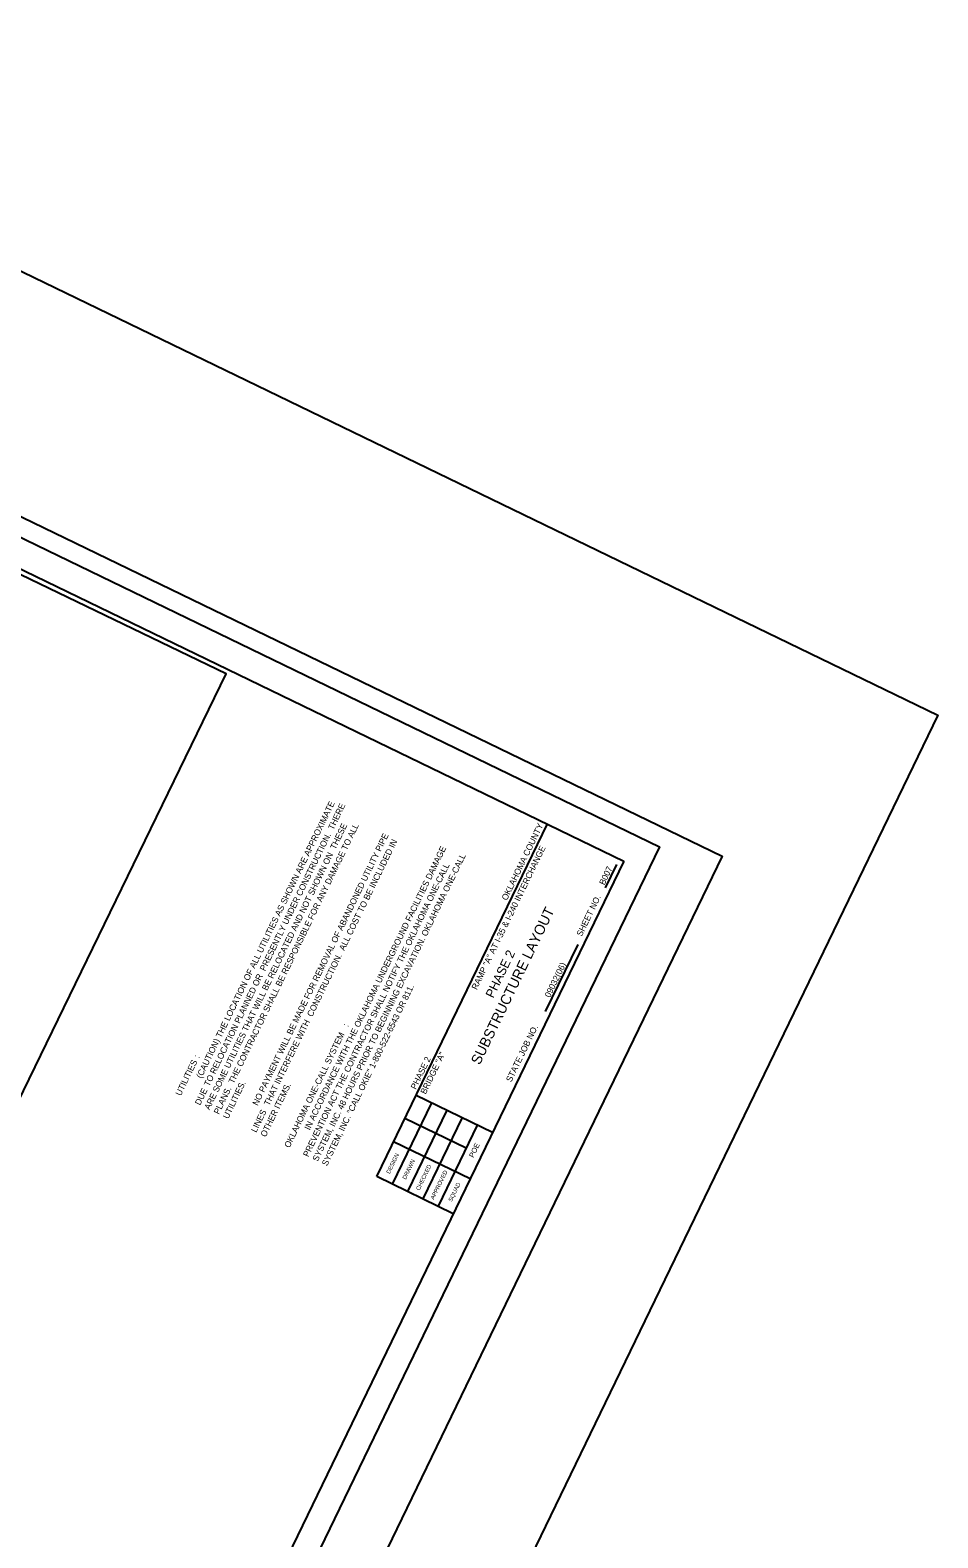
# Model space of a CAD drawing. Extents: x 2151051 to 2151774, y 141989 to 142830.
# Drawn here: x 2151509.7 to 2151773.9, y 142391.5 to 142830.1 of the extents above; entities that cross this region are included whole.
import ezdxf

# ---------------------------------------------------------------- set-up
doc = ezdxf.new("R2010")
doc.units = 0
for name, color, linetype in [('S', 7, 'Continuous'), ('SHT_Plot_Shape_Full', 7, 'Continuous'), ('SHT_Plot_Shape_Half', 7, 'Continuous'), ('SHT_Sheet_Border', 7, 'Continuous'), ('SHT_Standard_Sheet_Lines', 7, 'Continuous'), ('SHT_Standard_Sheet_Txt', 7, 'Continuous'), ('T', 7, 'Continuous'), ('T-Title', 7, 'Continuous')]:
    doc.layers.add(name, color=color, linetype=linetype)

msp = doc.modelspace()

# ---------------------------------------------------------------- linework, layer by layer
at = {"layer": 'Defpoints'}
msp.add_lwpolyline([(2151449.79, 142699.24), (2151417.91, 142565.6), (2151383.05, 142458.7), (2151328.99, 142351.22), (2151283.4, 142257.38), (2151361.04, 142219.8), (2151566.79, 142642.89)], close=True, dxfattribs=at)
at = {"layer": 'S'}
msp.add_lwpolyline([(2151051.5, 142188.16), (2151362.23, 142830.14), (2151773.92, 142630.87), (2151463.19, 141988.89)], close=True, dxfattribs=at)
at = {"layer": 'SHT_Plot_Shape_Full'}
msp.add_lwpolyline([(2151151.86, 142260.55), (2151387.12, 142746.61), (2151711.16, 142589.77), (2151475.89, 142103.71)], close=True, dxfattribs=at)
at = {"layer": 'SHT_Plot_Shape_Half'}
msp.add_lwpolyline([(2151173.7, 142277.27), (2151395.89, 142736.32), (2151692.92, 142592.55), (2151470.73, 142133.5)], close=True, dxfattribs=at)
at = {"layer": 'SHT_Sheet_Border'}
for p, q in [((2151610.63, 142496.57), (2151660.3, 142599.18)), ((2151644.35, 142509.41), (2151622.06, 142520.2)), ((2151632.91, 142485.78), (2151610.63, 142496.57))]:
    msp.add_line(p, q, dxfattribs=at)
msp.add_lwpolyline([(2151682.58, 142588.39), (2151476.72, 142163.09), (2151193.19, 142300.33), (2151399.05, 142725.63)], close=True, dxfattribs=at)
at = {"layer": 'SHT_Standard_Sheet_Lines'}
for p, q in [((2151677.2, 142580.59), (2151680.48, 142587.37)), ((2151659.78, 142544.61), (2151669.2, 142564.06)), ((2151636.62, 142504.82), (2151618.79, 142513.45)), ((2151637.81, 142495.91), (2151615.52, 142506.7))]:
    msp.add_line(p, q, dxfattribs=at)
for points in [[(2151626.53, 142518.04), (2151615.09, 142494.41)], [(2151630.98, 142515.88), (2151619.55, 142492.25)], [(2151635.44, 142513.72), (2151624, 142490.1)], [(2151639.89, 142511.57), (2151628.46, 142487.94)]]:
    msp.add_lwpolyline(points, dxfattribs=at)

# ---------------------------------------------------------------- texts
at = {"layer": 'Defpoints'}
msp.add_text('PHASE 2', height=2.625, rotation=64.172, dxfattribs=at).set_placement((2151644.52, 142548.31))
at = {"layer": 'SHT_Standard_Sheet_Txt'}
for s, height, p in [('SHEET NO. ', 1.8, (2151670.28, 142566.3)), ('STATE JOB NO.', 1.8, (2151649.76, 142523.91)), ('DESIGN', 1.2, (2151614.4, 142497.28)), ('DRAWN', 1.2, (2151619.09, 142495.61)), ('CHECKED', 1.2, (2151623.05, 142492.43)), ('APPROVED', 1.2, (2151627.26, 142489.75)), ('SQUAD', 1.2, (2151632.48, 142489.18))]:
    msp.add_text(s, height=height, rotation=64.172, dxfattribs=at).set_placement(p)
at = {"layer": 'T'}
for s, height, p in [('(CAUTION) THE LOCATION OF ALL UTILITIES AS SHOWN ARE APPROXIMATE ', 1.8, (2151559.62, 142524.98)), ('TO RELOCATION PLANNED OR  PRESENTLY UNDER CONSTRUCTION.  THERE ', 1.8, (2151561.86, 142522.64)), ('ARE SOME UTILITIES THAT WILL BE RELOCATED AND NOT SHOWN ON  THESE ', 1.8, (2151561.95, 142515.85)), ('PLANS.  THE CONTRACTOR SHALL BE RESPONSIBLE FOR ANY DAMAGE TO ALL ', 1.8, (2151564.69, 142514.52)), ('OKLAHOMA COUNTY', 1.8, (2151648.49, 142576.76)), ('NO PAYMENT WILL BE MADE FOR REMOVAL OF ABANDONED UTILITY PIPE ', 1.8, (2151575.97, 142517.06)), ('THAT INTERFERE WITH  CONSTRUCTION.  ALL COST TO BE INCLUDED IN ', 1.8, (2151579.32, 142517.03)), ('IN ACCORDANCE WITH THE OKLAHOMA UNDERGROUND FACILITIES DAMAGE ', 1.8, (2151591.1, 142509.95)), ('RAMP "A" AT I-35 & I-240 INTERCHANGE', 1.8, (2151639.74, 142550.76)), ('SYSTEM, INC. 48 HOURS PRIOR TO BEGINNING EXCAVATION. OKLAHOMA ONE-CALL ', 1.8, (2151593.43, 142500.82)), ('PREVENTION ACT THE CONTRACTOR SHALL NOTIFY THE OKLAHOMA ONE-CALL ', 1.8, (2151590.7, 142502.14)), ('B007', 1.8, (2151676.87, 142581.22)), ('09032(06)', 1.8, (2151661.03, 142548.49)), ('SYSTEM, INC. "CALL OKIE" 1-800-522-6543 OR 811.', 1.8, (2151596.17, 142499.5)), (':   ', 1.8, (2151602.27, 142540)), ('OKLAHOMA ONE-CALL SYSTEM', 1.8, (2151585.23, 142504.79)), (':    ', 1.8, (2151558.89, 142530.86)), ('PHASE 2', 1.8, (2151622.01, 142521.76)), ('BRIDGE "A"', 1.8, (2151624.86, 142520.37)), ('UTILITIES', 1.8, (2151553.58, 142519.9)), ('DUE ', 1.8, (2151559.22, 142517.17)), ('UTILITIES.    ', 1.8, (2151567.39, 142513.21)), ('OTHER ITEMS.   ', 1.8, (2151578.3, 142507.93)), ('LINES ', 1.8, (2151575.56, 142509.26)), ('POE', 1.5, (2151638.76, 142501.94))]:
    msp.add_text(s, height=height, rotation=64.172, dxfattribs=at).set_placement(p)
at = {"layer": 'T-Title'}
msp.add_text('SUBSTRUCTURE LAYOUT', height=3, rotation=64.172, dxfattribs=at).set_placement((2151640.59, 142528.87))

doc.saveas('drawing.dxf')
